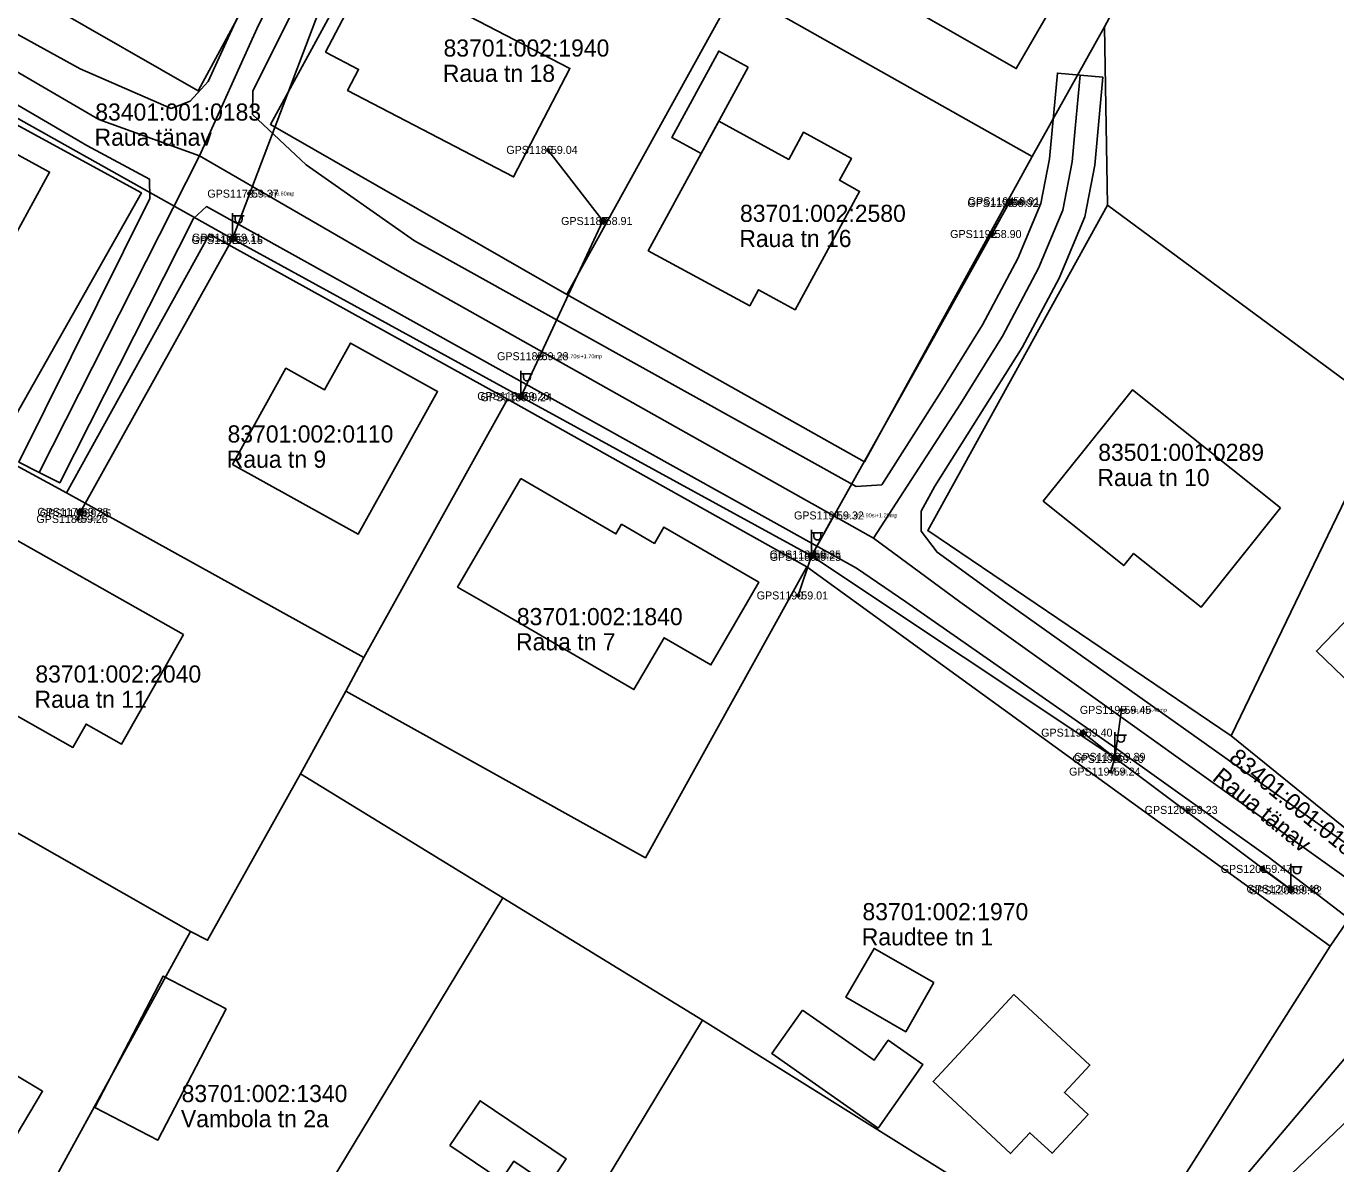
# Model space of a CAD drawing. Extents: x 580119 to 583377, y 6518915 to 6520820.
# Drawn here: x 581946.3 to 582060.9, y 6519950.8 to 6520050.4 of the extents above; entities that cross this region are included whole.
import ezdxf

# ---------------------------------------------------------------- set-up
doc = ezdxf.new("R2010")
doc.units = 0
for name, color, linetype in [('Hoone Elu- või ühiskondlik hoone', 7, 'Continuous'), ('Hoone Kõrval- või tootmishoone', 7, 'Continuous'), ('L_AADRESS', 7, 'Continuous'), ('MAAMUDEL', 7, 'Continuous'), ('MOOTKORG-EH2000', 7, 'Continuous'), ('MOOTMPUNKT', 7, 'Continuous'), ('MOOTNR', 7, 'Continuous'), ('MPOHULIIN', 7, 'Continuous'), ('PIIR', 7, 'Continuous'), ('POST', 7, 'Continuous'), ('Rippe kõrgus', 7, 'Continuous'), ('SIOHULIIN', 7, 'Continuous'), ('Tee Liiklusala', 7, 'Continuous'), ('Tee Tänav Kruuskate', 7, 'Continuous'), ('Tee Tänav Püsikate', 7, 'Continuous'), ('TUNNUS', 7, 'Continuous')]:
    doc.layers.add(name, color=color, linetype=linetype)

msp = doc.modelspace()

# ---------------------------------------------------------------- linework, layer by layer
at = {"layer": 'Hoone Elu- või ühiskondlik hoone'}
for points in [[(582036.39, 6520052.69), (582032.92, 6520046.66), (582019.95, 6520054.11), (582026.96, 6520066.32), (582036.22, 6520061.02), (582032.67, 6520054.82)], [(581972.51, 6520048.1), (581977.58, 6520057.79), (581982.96, 6520054.98), (581981.88, 6520052.92), (581993.89, 6520046.67), (581988.95, 6520037.19), (581974.44, 6520044.75), (581975.4, 6520046.59)], [(581929.73, 6520043.51), (581937.02, 6520039.52), (581937.76, 6520040.87), (581940.38, 6520039.44), (581941.44, 6520041.38), (581948.37, 6520037.6), (581944.08, 6520029.74), (581942.67, 6520030.51), (581940.77, 6520027.04), (581939.19, 6520027.91), (581937.62, 6520025.05), (581923.77, 6520032.61)], [(582006.91, 6520042.05), (582013.02, 6520038.72), (582014.31, 6520041.09), (582018.5, 6520038.81), (582017.45, 6520036.89), (582019.22, 6520035.92), (582013.57, 6520025.57), (582010.38, 6520027.31), (582009.61, 6520025.9), (582000.74, 6520030.73), (582005.37, 6520039.23)], [(581964.36, 6520012.04), (581969.04, 6520020.44), (581972.42, 6520018.56), (581974.7, 6520022.65), (581982.31, 6520018.41), (581975.35, 6520005.92)], [(582056.02, 6520008.23), (582049.08, 6519999.54), (582043.19, 6520004.25), (582042.32, 6520003.18), (582035.28, 6520008.82), (582043.09, 6520018.56)], [(581989.59, 6520010.8), (581997.91, 6520005.96), (581998.4, 6520006.8), (582001.28, 6520005.13), (582002.11, 6520006.55), (582010.41, 6520001.72), (582009.41, 6520000), (582006.21, 6519994.5), (582002.12, 6519996.87), (581999.48, 6519992.34), (581986.31, 6520000), (581984.06, 6520001.31)], [(582079.99, 6520002.18), (582065.36, 6519987), (582063.25, 6519989.04), (582064.62, 6519990.45), (582059.17, 6519995.7), (582072.44, 6520009.46)], [(581960.08, 6519997.16), (581954.67, 6519987.57), (581951.57, 6519989.32), (581950.41, 6519987.27), (581942.97, 6519991.47), (581944.36, 6519993.95), (581940.12, 6519996.34), (581941.5, 6519998.79), (581939.36, 6520000), (581943.16, 6520006.72)], [(582032.72, 6519965.65), (582039.37, 6519959.48), (582037.14, 6519957.09), (582039.21, 6519955.17), (582036.06, 6519951.77), (582034.12, 6519953.57), (582032.43, 6519951.75), (582025.65, 6519958.05)], [(581937.19, 6519963.52), (581947.76, 6519957.2), (581941.46, 6519946.66), (581930.88, 6519952.98), (581933.52, 6519957.4), (581931.95, 6519958.33), (581934.12, 6519961.94), (581935.69, 6519961)]]:
    msp.add_lwpolyline(points, close=True, dxfattribs=at)
at = {"layer": 'Hoone Kõrval- või tootmishoone'}
for points in [[(582009.48, 6520046.78), (582005.37, 6520039.23), (582002.79, 6520040.64), (582006.9, 6520048.19)], [(582025.71, 6519966.7), (582023.25, 6519962.41), (582018.02, 6519965.42), (582020.48, 6519969.7)], [(581963.83, 6519964.4), (581957.84, 6519952.91), (581952.33, 6519955.77), (581958.31, 6519967.28)], [(582014.23, 6519964.3), (582020.48, 6519959.91), (582021.72, 6519961.67), (582024.74, 6519959.55), (582020.84, 6519953.98), (582011.55, 6519960.49)], [(581983.37, 6519952.45), (581986.02, 6519956.37), (581993.56, 6519951.28), (581992.03, 6519949.01), (581988.97, 6519951.07), (581987.86, 6519949.42)]]:
    msp.add_lwpolyline(points, close=True, dxfattribs=at)
at = {"layer": 'MOOTMPUNKT'}
for centre in [(581991.96, 6520039.55), (581965.81, 6520035.72), (582032.27, 6520034.9), (582032.4, 6520035.06), (581996.75, 6520033.33), (581964.33, 6520031.87), (582030.78, 6520032.19), (581964.43, 6520031.67), (581991.15, 6520021.5), (581989.49, 6520018.01), (581989.71, 6520017.91), (581950.94, 6520007.88), (581951.16, 6520007.75), (581950.86, 6520007.26), (582016.98, 6520007.57), (582014.99, 6520004.15), (582015, 6520003.95), (582013.86, 6520000.57), (582042.12, 6519990.56), (582038.74, 6519988.57), (582041.47, 6519986.27), (582041.62, 6519986.45), (582041.18, 6519985.16), (582047.93, 6519981.81), (582054.44, 6519976.65), (582056.84, 6519974.9), (582057.05, 6519974.77)]:
    msp.add_circle(centre, 0.1, dxfattribs=at)
at = {"layer": 'MPOHULIIN'}
for p, q in [((582032.34, 6520034.98), (582015, 6520004.05)), ((582016.98, 6520007.57), (582015, 6520004.05)), ((582042.12, 6519990.56), (582041.55, 6519986.36))]:
    msp.add_line(p, q, dxfattribs=at)
for points in [[(581854.23, 6520098.42), (581869.03, 6520084.64), (581898.23, 6520068.44), (581929.76, 6520051.17), (581964.38, 6520031.77), (581989.6, 6520017.96), (582015, 6520004.05), (582041.55, 6519986.36), (582056.94, 6519974.84)], [(581950.86, 6520007.26), (581951.05, 6520007.82), (581964.38, 6520031.77), (581978.64, 6520069.34)], [(581859.1, 6519746.43), (581883.65, 6519775.9), (581910.63, 6519803.45), (581938.38, 6519831.71), (581969.55, 6519863.69), (582004.1, 6519898.63), (582043.97, 6519939.12), (582079.7, 6519981.43), (582116.09, 6520024.19), (582121.9, 6520051.43)], [(581989.6, 6520017.96), (581996.75, 6520033.33), (581991.96, 6520039.55)]]:
    msp.add_lwpolyline(points, dxfattribs=at)
at = {"layer": 'PIIR'}
for points in [[(582040.64, 6520050.31), (582046.31, 6520060.89), (582047.03, 6520060.45), (582064.17, 6520093.83), (582096.36, 6520074.44), (582074.87, 6520034.25), (582065.39, 6520016.62), (582040.9, 6520034.7)], [(581975.85, 6520071.52), (581961.38, 6520044.71), (581935.27, 6520059.68), (581949.99, 6520086.2)], [(582020.31, 6520075.42), (582046.31, 6520060.89), (582040.64, 6520050.31), (582034.3, 6520038.98), (582008.37, 6520053.62)], [(581982, 6520068.01), (582008.37, 6520053.62), (581993.62, 6520026.9), (581967.69, 6520041.77)], [(582034.3, 6520038.98), (582019.64, 6520012.26), (581993.62, 6520026.9), (582008.37, 6520053.62)], [(581930.04, 6520050.18), (581956.4, 6520035.78), (581943.51, 6520012.98), (581940.76, 6520014.9), (581917.35, 6520027.64)], [(582051.72, 6519988.28), (582025.18, 6520006.25), (582040.9, 6520034.7), (582065.39, 6520016.62)], [(582065.39, 6520016.62), (582074.87, 6520034.25), (582105.65, 6520019.17), (582065.39, 6519977.21), (582051.72, 6519988.28)], [(581962.35, 6520032.18), (581988.42, 6520017.74), (581975.86, 6519995.13), (581949.86, 6520009.55)], [(581975.86, 6519995.13), (581988.42, 6520017.74), (582014.59, 6520003.08), (582000.48, 6519977.62), (581974.28, 6519992.2)], [(581940.76, 6520014.9), (581943.51, 6520012.98), (581949.86, 6520009.55), (581975.86, 6519995.13), (581974.28, 6519992.2), (581970.31, 6519984.96), (581962.19, 6519970.41), (581960.69, 6519971.17), (581928.6, 6519989.46)], [(581988.02, 6519974.12), (581970.31, 6519984.96), (581974.28, 6519992.2), (582000.48, 6519977.62), (582014.59, 6520003.08), (582060.37, 6519969.9), (582041.82, 6519940.66), (582005.49, 6519963.42)], [(581928.6, 6519989.46), (581960.69, 6519971.17), (581942.22, 6519937.53), (581911.11, 6519957.21)], [(581960.69, 6519971.17), (581962.19, 6519970.41), (581970.31, 6519984.96), (581988.02, 6519974.12), (581960.1, 6519927.96), (581942.22, 6519937.53)], [(581988.02, 6519974.12), (582005.49, 6519963.42), (581977.62, 6519917.23), (581960.1, 6519927.96)], [(582005.49, 6519963.42), (582041.82, 6519940.66), (582003.25, 6519901.7), (581977.62, 6519917.23)]]:
    msp.add_lwpolyline(points, close=True, dxfattribs=at)
for points in [[(581935.27, 6520059.68), (581961.38, 6520044.71), (581975.85, 6520071.52), (581978.94, 6520069.81), (581982, 6520068.01), (581967.69, 6520041.77), (581993.62, 6520026.9), (582019.64, 6520012.26), (582034.3, 6520038.98), (582040.64, 6520050.31), (582040.9, 6520034.7), (582025.18, 6520006.25), (582051.72, 6519988.28), (582065.39, 6519977.21), (582060.37, 6519969.9), (582014.59, 6520003.08), (581988.42, 6520017.74), (581962.35, 6520032.18), (581949.86, 6520009.55), (581943.51, 6520012.98), (581956.4, 6520035.78), (581930.04, 6520050.18)], [(581942.19, 6519843.34), (581946.33, 6519843.38), (581968.11, 6519864.42), (581994.57, 6519891.85), (582003.25, 6519901.7), (582041.82, 6519940.66), (582060.37, 6519969.9), (582065.39, 6519977.21), (582094.14, 6519961.8), (582143.96, 6519961.25), (582189.08, 6519960.22), (582226.48, 6519959.63), (582241.09, 6519960.09), (582268.53, 6519957.77), (582295.04, 6519956.63)]]:
    msp.add_lwpolyline(points, dxfattribs=at)
at = {"layer": 'POST'}
for p, q in [((581964.38, 6520032.02), (581964.38, 6520034.02)), ((581964.38, 6520033.77), (581965.38, 6520033.77)), ((581964.6, 6520033.45), (581964.6, 6520033.77)), ((581965.22, 6520033.45), (581965.22, 6520033.77)), ((581964.38, 6520031.77), (581964.38, 6520031.77)), ((581989.6, 6520018.21), (581989.6, 6520020.21)), ((581989.6, 6520019.96), (581990.6, 6520019.96)), ((581989.82, 6520019.64), (581989.82, 6520019.96)), ((581990.44, 6520019.64), (581990.44, 6520019.96)), ((581989.6, 6520017.96), (581989.6, 6520017.96)), ((582015, 6520004.3), (582015, 6520006.3)), ((582015, 6520006.05), (582016, 6520006.05)), ((582015.22, 6520005.73), (582015.22, 6520006.05)), ((582015.84, 6520005.73), (582015.84, 6520006.05)), ((582015, 6520004.05), (582015, 6520004.05)), ((582041.55, 6519986.61), (582041.55, 6519988.61)), ((582041.55, 6519988.36), (582042.55, 6519988.36)), ((582041.77, 6519988.04), (582041.77, 6519988.36)), ((582042.39, 6519988.04), (582042.39, 6519988.36)), ((582041.55, 6519986.36), (582041.55, 6519986.36)), ((582056.94, 6519975.09), (582056.94, 6519977.09)), ((582056.94, 6519976.84), (582057.94, 6519976.84)), ((582057.17, 6519976.52), (582057.17, 6519976.84)), ((582057.78, 6519976.52), (582057.78, 6519976.84)), ((582056.94, 6519974.84), (582056.94, 6519974.84))]:
    msp.add_line(p, q, dxfattribs=at)
for points in [[(582032.34, 6520034.98), (582030.78, 6520032.19)], [(582013.86, 6520000.57), (582015, 6520004.05)], [(582038.74, 6519988.57), (582041.55, 6519986.36)], [(582054.44, 6519976.65), (582056.94, 6519974.84)]]:
    msp.add_lwpolyline(points, dxfattribs=at)
for centre, radius in [((582032.34, 6520034.98), 0.25), ((581996.75, 6520033.33), 0.25), ((581964.38, 6520031.77), 0.25), ((582030.78, 6520032.19), 0.2), ((581989.6, 6520017.96), 0.25), ((581951.05, 6520007.82), 0.25), ((582015, 6520004.05), 0.25), ((582013.86, 6520000.57), 0.125), ((582013.86, 6520000.57), 0.105), ((582013.86, 6520000.57), 0.0851), ((582013.86, 6520000.57), 0.0651), ((582013.86, 6520000.57), 0.0451), ((582013.86, 6520000.57), 0.0251), ((582013.86, 6520000.57), 0.00511), ((582038.74, 6519988.57), 0.2), ((582041.55, 6519986.36), 0.25), ((582054.44, 6519976.65), 0.2), ((582056.94, 6519974.84), 0.25)]:
    msp.add_circle(centre, radius, dxfattribs=at)
for centre in [(581964.91, 6520033.45), (581990.13, 6520019.64), (582015.53, 6520005.73), (582042.08, 6519988.04), (582057.48, 6519976.52)]:
    msp.add_arc(centre, 0.306, 180, 0, dxfattribs=at)
at = {"layer": 'SIOHULIIN'}
for p, q in [((582015, 6520004.05), (582032.34, 6520034.98)), ((581996.75, 6520033.33), (581989.6, 6520017.96))]:
    msp.add_line(p, q, dxfattribs=at)
msp.add_lwpolyline([(582041.18, 6519985.16), (582041.55, 6519986.36), (582015, 6520004.05), (581989.6, 6520017.96), (581964.38, 6520031.77), (581929.76, 6520051.17), (581898.23, 6520068.44), (581869.03, 6520084.64)], dxfattribs=at)
at = {"layer": 'Tee Liiklusala'}
for points in [[(581978.53, 6520069.59), (581966.14, 6520044.68), (581966.11, 6520042.65), (581970.81, 6520038.25), (581980.3, 6520031.6), (582018.91, 6520010.11), (582021.16, 6520010.26), (582026.36, 6520018.41), (582029.97, 6520024.25), (582033.06, 6520030.05), (582035.08, 6520034.85), (582035.82, 6520038.77), (582036.52, 6520046.27), (582038.51, 6520046.08), (582040.5, 6520045.9), (582039.78, 6520038.21), (582038.93, 6520033.69), (582036.68, 6520028.33), (582033.44, 6520022.25), (582025.8, 6520010.12), (582024.6, 6520007.94), (582024.6, 6520006.2), (582025.99, 6520004.35), (582031.99, 6520000), (582063.11, 6519977.9)], [(581933.43, 6520056.35), (581951.04, 6520046.63), (581959.01, 6520043.18), (581960.66, 6520043.8), (581962.23, 6520045.52), (581965.43, 6520052.46)], [(581833.17, 6520000), (581968.76, 6519918.78), (581994.48, 6519901.93), (582000.62, 6519898.5), (582003.77, 6519898.5), (582051.89, 6519945.09), (582069.67, 6519962.07), (582069.67, 6519964.27), (582068.75, 6519966.35), (582066.89, 6519968.55), (582060.4, 6519973.54), (582054.96, 6519977.71), (582041.63, 6519987.2), (582023.26, 6520000), (582018.96, 6520002.96), (581962.1, 6520034.59), (581960.96, 6520033.54), (581949.26, 6520010.42), (581947.47, 6520011.33), (581945.69, 6520012.23), (581957.15, 6520035.29), (581957.11, 6520036.99), (581951.62, 6520039.93), (581930.6, 6520052.21)]]:
    msp.add_lwpolyline(points, dxfattribs=at)
at = {"layer": 'Tee Tänav Kruuskate'}
for points in [[(581961.49, 6520039.04), (581966.64, 6520050.45), (581976.74, 6520070.49)], [(582020.43, 6520005.57), (582028.05, 6520017.34), (582031.71, 6520023.25), (582034.87, 6520029.19), (582037, 6520034.27), (582037.8, 6520038.49), (582038.08, 6520041.43), (582038.51, 6520046.08)], [(581947.47, 6520011.33), (581961.49, 6520039.04)]]:
    msp.add_lwpolyline(points, dxfattribs=at)
at = {"layer": 'Tee Tänav Püsikate'}
for points in [[(581905.64, 6520071.7), (581919.26, 6520064.4), (581932.02, 6520054.28), (581952.69, 6520042.2), (581961.49, 6520039.04)], [(582020.43, 6520005.57), (581978.81, 6520028.99), (581961.49, 6520039.04)], [(582075.67, 6519963.66), (582070.48, 6519968.9), (582064.23, 6519974.12), (582028, 6520000), (582020.43, 6520005.57)]]:
    msp.add_lwpolyline(points, dxfattribs=at)

# ---------------------------------------------------------------- texts
at = {"layer": 'L_AADRESS'}
for s, p in [('Raua tn 18', (581982.77, 6520045.5)), ('Raua tänav', (581952.31, 6520039.91)), ('Raua tn 16', (582008.7, 6520031.05)), ('Raua tn 9', (581963.87, 6520011.74)), ('Raua tn 10', (582040.02, 6520010.14)), ('Raua tn 7', (581989.17, 6519995.77)), ('Raua tn 11', (581947.06, 6519990.74)), ('Raudtee tn 1', (582019.41, 6519969.96)), ('Vambola tn 2a', (581959.86, 6519954.05))]:
    msp.add_text(s, height=1.5, dxfattribs=at).set_placement(p)
msp.add_text('Raua tänav', height=1.5, rotation=320.8559, dxfattribs=at).set_placement((582049.98, 6519984.47))
at = {"layer": 'MAAMUDEL'}
for s, p in [(' kaabel', (582032.4, 6520034.89)), (' kaabel', (582032.27, 6520034.72)), (' mp_ohl', (581950.86, 6520007.09)), (' si', (582014.99, 6520003.98)), (' kaabel', (582014.99, 6520003.98)), (' si', (582015, 6520003.78)), (' kaabel', (582015, 6520003.78)), (' si', (582041.47, 6519986.09)), (' si', (582041.62, 6519986.28)), (' si_ohl', (582041.18, 6519984.98)), (' tv', (582047.93, 6519981.63))]:
    msp.add_text(s, height=0.35, dxfattribs=at).set_placement(p)
at = {"layer": 'MOOTKORG-EH2000'}
for s, p in [(' 59.04', (581991.96, 6520039.2)), (' 59.37', (581965.81, 6520035.37)), (' 58.92', (582032.27, 6520034.55)), (' 58.91', (582032.4, 6520034.71)), (' 58.91', (581996.75, 6520032.98)), (' 59.11', (581964.33, 6520031.52)), (' 59.15', (581964.43, 6520031.32)), (' 58.90', (582030.78, 6520031.84)), (' 59.28', (581991.15, 6520021.15)), (' 59.20', (581989.49, 6520017.66)), (' 59.24', (581989.71, 6520017.56)), (' 59.25', (581950.94, 6520007.53)), (' 59.25', (581951.16, 6520007.4)), (' 59.32', (582016.98, 6520007.22)), (' 59.26', (581950.86, 6520006.91)), (' 59.25', (582014.99, 6520003.8)), (' 59.25', (582015, 6520003.6)), (' 59.01', (582013.86, 6520000.22)), (' 59.45', (582042.12, 6519990.21)), (' 59.40', (582038.74, 6519988.22)), (' 59.40', (582041.47, 6519985.92)), (' 59.39', (582041.62, 6519986.1)), (' 59.24', (582041.18, 6519984.81)), (' 59.23', (582047.93, 6519981.46)), (' 59.47', (582054.44, 6519976.3)), (' 59.48', (582056.84, 6519974.55)), (' 59.42', (582057.05, 6519974.42))]:
    msp.add_text(s, height=0.7, dxfattribs=at).set_placement(p)
at = {"layer": 'MOOTNR'}
for s, p in [('GPS1186 ', (581988.32, 6520039.2)), ('GPS1173 ', (581962.17, 6520035.37)), ('GPS1193 ', (582028.64, 6520034.55)), ('GPS1194 ', (582028.69, 6520034.71)), ('GPS1187 ', (581993.11, 6520032.98)), ('GPS1182 ', (581960.79, 6520031.32)), ('GPS1181 ', (581960.83, 6520031.52)), ('GPS1192 ', (582027.14, 6520031.84)), ('GPS1185 ', (581987.51, 6520021.15)), ('GPS1184 ', (581985.78, 6520017.66)), ('GPS1183 ', (581986.07, 6520017.56)), ('GPS1179 ', (581947.3, 6520007.53)), ('GPS1178 ', (581947.52, 6520007.4)), ('GPS1191 ', (582013.48, 6520007.22)), ('GPS1180 ', (581947.22, 6520006.91)), ('GPS1188 ', (582011.35, 6520003.8)), ('GPS1189 ', (582011.36, 6520003.6)), ('GPS1190 ', (582010.22, 6520000.22)), ('GPS1195 ', (582038.48, 6519990.21)), ('GPS1196 ', (582035.1, 6519988.22)), ('GPS1198 ', (582037.83, 6519985.92)), ('GPS1199 ', (582037.98, 6519986.1)), ('GPS1197 ', (582037.54, 6519984.81)), ('GPS1200 ', (582044.15, 6519981.46)), ('GPS1201 ', (582050.8, 6519976.3)), ('GPS1202 ', (582053.06, 6519974.55)), ('GPS1203 ', (582053.27, 6519974.42))]:
    msp.add_text(s, height=0.7, dxfattribs=at).set_placement(p)
at = {"layer": 'Rippe kõrgus'}
for s, p in [(' el_mp_ohl6.60mp', (581965.81, 6520035.55)), (' el_mp_ohl4.70si+1.70mp', (581991.15, 6520021.32)), (' el_mp_ohl4.90si+1.20mp', (582016.98, 6520007.4)), (' el_mp_ohl5.40mp', (582042.12, 6519990.38))]:
    msp.add_text(s, height=0.35, dxfattribs=at).set_placement(p)
at = {"layer": 'TUNNUS'}
for s, p in [('83701:002:1940', (581982.83, 6520047.71)), ('83401:001:0183', (581952.37, 6520042.11)), ('83701:002:2580', (582008.76, 6520033.25)), ('83701:002:0110', (581963.94, 6520013.95)), ('83501:001:0289', (582040.09, 6520012.34)), ('83701:002:1840', (581989.24, 6519997.97)), ('83701:002:2040', (581947.13, 6519992.95)), ('83701:002:1970', (582019.47, 6519972.16)), ('83701:002:1340', (581959.92, 6519956.25))]:
    msp.add_text(s, height=1.5, dxfattribs=at).set_placement(p)
msp.add_text('83401:001:0183', height=1.5, rotation=320.8559, dxfattribs=at).set_placement((582051.42, 6519986.14))

doc.saveas('drawing.dxf')
